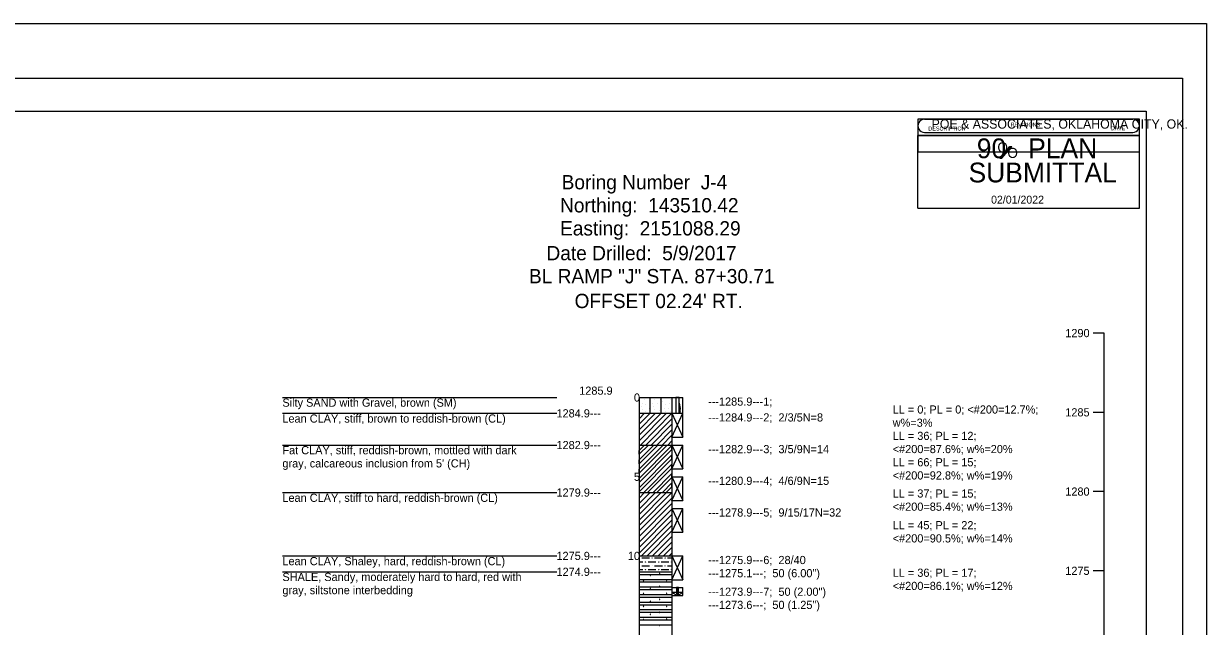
# Model space of a CAD drawing. Extents: x 2150148.6 to 2150220.1, y 143803.7 to 143875.1.
# Drawn here: x 2150182.61 to 2150200.57, y 143824.55 to 143833.69 of the extents above; entities that cross this region are included whole.
import ezdxf

# ---------------------------------------------------------------- set-up
doc = ezdxf.new("R2010")
doc.units = 0
for name, color, linetype in [('Default', 7, 'Continuous'), ('SHT_Plot_Shape_Full', 7, 'Continuous'), ('SHT_Plot_Shape_Half', 7, 'Continuous'), ('SHT_Sheet_Border', 7, 'Continuous'), ('SHT_Stamp_90_Submit', 7, 'Continuous'), ('SHT_Stamp_Rev_Block', 7, 'Continuous')]:
    doc.layers.add(name, color=color, linetype=linetype)

# ---------------------------------------------------------------- blocks, each defined once
blk = doc.blocks.new('POINT_DISPLAY')
at = {"layer": 'Default'}
blk.add_line((0, 0), (0, 0), dxfattribs=at)

msp = doc.modelspace()

# ---------------------------------------------------------------- linework, layer by layer
at = {"layer": 'Default'}
msp.add_line((2150199.025, 143815.773), (2150199.025, 143828.994), dxfattribs=at)
for points in [[(2150199.025, 143828.994), (2150198.858, 143828.994)], [(2150186.544, 143828.017), (2150190.71, 143828.017)], [(2150191.96, 143828.017), (2150191.96, 143817.921)], [(2150191.96, 143828.017), (2150192.46, 143828.017)], [(2150192.127, 143827.777), (2150192.127, 143828.017)], [(2150192.294, 143827.777), (2150192.294, 143828.017)], [(2150192.46, 143828.017), (2150192.627, 143828.017)], [(2150192.46, 143828.017), (2150192.46, 143817.921)], [(2150192.627, 143827.777), (2150192.627, 143828.017)], [(2150186.544, 143827.777), (2150190.71, 143827.777)], [(2150191.96, 143827.777), (2150192.46, 143827.777)], [(2150191.96, 143827.694), (2150192.044, 143827.777)], [(2150191.96, 143827.61), (2150192.127, 143827.777)], [(2150191.96, 143827.527), (2150192.21, 143827.777)], [(2150191.96, 143827.444), (2150192.294, 143827.777)], [(2150191.96, 143827.36), (2150192.377, 143827.777)], [(2150191.98, 143827.296), (2150192.46, 143827.777)], [(2150192.063, 143827.296), (2150192.46, 143827.694)], [(2150192.46, 143827.777), (2150192.627, 143827.777)], [(2150192.46, 143827.777), (2150192.627, 143827.416)], [(2150192.46, 143827.416), (2150192.627, 143827.777)], [(2150192.46, 143827.777), (2150192.627, 143827.777)], [(2150192.627, 143827.416), (2150192.627, 143827.777)], [(2150199.025, 143827.792), (2150198.858, 143827.792)], [(2150192.146, 143827.296), (2150192.46, 143827.61)], [(2150192.23, 143827.296), (2150192.46, 143827.527)], [(2150186.544, 143827.296), (2150190.71, 143827.296)], [(2150191.96, 143827.296), (2150192.46, 143827.296)], [(2150192.313, 143827.296), (2150192.46, 143827.444)], [(2150192.396, 143827.296), (2150192.46, 143827.36)], [(2150192.46, 143827.416), (2150192.627, 143827.416)], [(2150192.46, 143827.296), (2150192.627, 143826.936)], [(2150192.46, 143826.936), (2150192.627, 143827.296)], [(2150192.46, 143827.296), (2150192.627, 143827.296)], [(2150192.627, 143826.936), (2150192.627, 143827.296)], [(2150192.46, 143826.936), (2150192.627, 143826.936)], [(2150192.46, 143826.815), (2150192.627, 143826.455)], [(2150192.46, 143826.455), (2150192.627, 143826.815)], [(2150192.46, 143826.815), (2150192.627, 143826.815)], [(2150192.627, 143826.455), (2150192.627, 143826.815)], [(2150186.544, 143826.575), (2150190.71, 143826.575)], [(2150191.96, 143826.575), (2150192.46, 143826.575)], [(2150191.96, 143826.492), (2150192.044, 143826.575)], [(2150191.96, 143826.408), (2150192.127, 143826.575)], [(2150191.96, 143826.325), (2150192.21, 143826.575)], [(2150191.96, 143826.242), (2150192.294, 143826.575)], [(2150191.96, 143826.158), (2150192.377, 143826.575)], [(2150191.96, 143826.075), (2150192.46, 143826.575)], [(2150199.025, 143826.59), (2150198.858, 143826.59)], [(2150191.96, 143825.992), (2150192.46, 143826.492)], [(2150191.96, 143825.908), (2150192.46, 143826.408)], [(2150192.46, 143826.455), (2150192.627, 143826.455)], [(2150191.96, 143825.825), (2150192.46, 143826.325)], [(2150191.96, 143825.742), (2150192.46, 143826.242)], [(2150192.46, 143826.335), (2150192.627, 143825.974)], [(2150192.46, 143825.974), (2150192.627, 143826.335)], [(2150192.46, 143826.335), (2150192.627, 143826.335)], [(2150192.627, 143825.974), (2150192.627, 143826.335)], [(2150191.96, 143825.658), (2150192.46, 143826.158)], [(2150191.999, 143825.614), (2150192.46, 143826.075)], [(2150192.082, 143825.614), (2150192.46, 143825.992)], [(2150192.166, 143825.614), (2150192.46, 143825.908)], [(2150192.46, 143825.974), (2150192.627, 143825.974)], [(2150192.249, 143825.614), (2150192.46, 143825.825)], [(2150192.332, 143825.614), (2150192.46, 143825.742)], [(2150186.544, 143825.614), (2150190.71, 143825.614)], [(2150191.96, 143825.614), (2150192.46, 143825.614)], [(2150191.96, 143825.584), (2150191.964, 143825.584), (2150191.964, 143825.58), (2150191.96, 143825.584)], [(2150191.96, 143825.525), (2150192.019, 143825.525)], [(2150192, 143825.584), (2150192.118, 143825.584)], [(2150192.059, 143825.525), (2150192.063, 143825.525), (2150192.059, 143825.521), (2150192.059, 143825.525)], [(2150192.098, 143825.525), (2150192.216, 143825.525)], [(2150192.157, 143825.584), (2150192.161, 143825.584), (2150192.157, 143825.58), (2150192.157, 143825.584)], [(2150192.197, 143825.584), (2150192.315, 143825.584)], [(2150192.256, 143825.525), (2150192.26, 143825.525), (2150192.26, 143825.521), (2150192.256, 143825.525)], [(2150192.295, 143825.525), (2150192.354, 143825.525)], [(2150192.354, 143825.584), (2150192.358, 143825.584), (2150192.358, 143825.58), (2150192.354, 143825.584)], [(2150192.354, 143825.525), (2150192.413, 143825.525)], [(2150192.393, 143825.584), (2150192.46, 143825.584)], [(2150192.416, 143825.614), (2150192.46, 143825.658)], [(2150192.453, 143825.525), (2150192.456, 143825.525), (2150192.453, 143825.521), (2150192.453, 143825.525)], [(2150192.46, 143825.614), (2150192.627, 143825.253)], [(2150192.46, 143825.253), (2150192.627, 143825.614)], [(2150192.46, 143825.614), (2150192.627, 143825.614)], [(2150192.627, 143825.253), (2150192.627, 143825.614)], [(2150186.544, 143825.373), (2150190.71, 143825.373)], [(2150191.96, 143825.466), (2150191.964, 143825.466), (2150191.964, 143825.462), (2150191.96, 143825.466)], [(2150191.96, 143825.407), (2150192.019, 143825.407)], [(2150191.96, 143825.373), (2150192.46, 143825.373)], [(2150191.96, 143825.373), (2150192.46, 143825.373)], [(2150191.96, 143825.334), (2150192.46, 143825.334)], [(2150192, 143825.466), (2150192.118, 143825.466)], [(2150192.059, 143825.407), (2150192.063, 143825.407), (2150192.059, 143825.403), (2150192.059, 143825.407)], [(2150192.098, 143825.407), (2150192.216, 143825.407)], [(2150192.135, 143825.317), (2150192.134, 143825.32), (2150192.131, 143825.32), (2150192.129, 143825.317), (2150192.131, 143825.315), (2150192.134, 143825.315), (2150192.135, 143825.317)], [(2150192.157, 143825.466), (2150192.161, 143825.466), (2150192.157, 143825.462), (2150192.157, 143825.466)], [(2150192.197, 143825.466), (2150192.315, 143825.466)], [(2150192.256, 143825.407), (2150192.26, 143825.407), (2150192.26, 143825.403), (2150192.256, 143825.407)], [(2150192.278, 143825.349), (2150192.276, 143825.352), (2150192.273, 143825.352), (2150192.272, 143825.349), (2150192.273, 143825.346), (2150192.276, 143825.346), (2150192.278, 143825.349)], [(2150192.295, 143825.407), (2150192.354, 143825.407)], [(2150192.354, 143825.466), (2150192.358, 143825.466), (2150192.358, 143825.462), (2150192.354, 143825.466)], [(2150192.354, 143825.407), (2150192.413, 143825.407)], [(2150192.393, 143825.466), (2150192.46, 143825.466)], [(2150192.453, 143825.407), (2150192.456, 143825.407), (2150192.453, 143825.403), (2150192.453, 143825.407)], [(2150199.025, 143825.388), (2150198.858, 143825.388)], [(2150191.96, 143825.258), (2150192.46, 143825.258)], [(2150191.96, 143825.219), (2150192.46, 143825.219)], [(2150191.96, 143825.144), (2150192.46, 143825.144)], [(2150192.031, 143825.238), (2150192.029, 143825.241), (2150192.026, 143825.241), (2150192.024, 143825.238), (2150192.026, 143825.236), (2150192.029, 143825.236), (2150192.031, 143825.238)], [(2150192.135, 143825.12), (2150192.134, 143825.123), (2150192.131, 143825.123), (2150192.129, 143825.121), (2150192.131, 143825.118), (2150192.134, 143825.118), (2150192.135, 143825.12)], [(2150192.278, 143825.152), (2150192.276, 143825.155), (2150192.273, 143825.155), (2150192.272, 143825.152), (2150192.273, 143825.15), (2150192.276, 143825.15), (2150192.278, 143825.152)], [(2150192.384, 143825.245), (2150192.382, 143825.248), (2150192.379, 143825.248), (2150192.377, 143825.245), (2150192.379, 143825.242), (2150192.382, 143825.242), (2150192.384, 143825.245)], [(2150192.46, 143825.253), (2150192.627, 143825.253)], [(2150192.46, 143825.133), (2150192.627, 143825.133)], [(2150192.627, 143825.013), (2150192.627, 143825.133)], [(2150191.96, 143825.104), (2150192.46, 143825.104)], [(2150191.96, 143825.029), (2150192.46, 143825.029)], [(2150191.96, 143824.989), (2150192.46, 143824.989)], [(2150192.031, 143825.042), (2150192.029, 143825.044), (2150192.026, 143825.044), (2150192.024, 143825.042), (2150192.026, 143825.039), (2150192.029, 143825.039), (2150192.031, 143825.042)], [(2150192.278, 143824.956), (2150192.276, 143824.958), (2150192.273, 143824.958), (2150192.272, 143824.956), (2150192.273, 143824.953), (2150192.276, 143824.953), (2150192.278, 143824.956)], [(2150192.384, 143825.048), (2150192.382, 143825.051), (2150192.379, 143825.051), (2150192.377, 143825.048), (2150192.379, 143825.045), (2150192.382, 143825.045), (2150192.384, 143825.048)], [(2150192.46, 143825.013), (2150192.627, 143825.013)], [(2150191.96, 143824.914), (2150192.46, 143824.914)], [(2150191.96, 143824.874), (2150192.46, 143824.874)], [(2150191.96, 143824.799), (2150192.46, 143824.799)], [(2150192.031, 143824.845), (2150192.029, 143824.848), (2150192.026, 143824.848), (2150192.024, 143824.845), (2150192.026, 143824.842), (2150192.029, 143824.842), (2150192.031, 143824.845)], [(2150192.135, 143824.924), (2150192.134, 143824.927), (2150192.131, 143824.927), (2150192.129, 143824.924), (2150192.131, 143824.921), (2150192.134, 143824.921), (2150192.135, 143824.924)], [(2150192.384, 143824.851), (2150192.382, 143824.854), (2150192.379, 143824.854), (2150192.377, 143824.851), (2150192.379, 143824.848), (2150192.382, 143824.848), (2150192.384, 143824.851)], [(2150191.96, 143824.76), (2150192.46, 143824.76)], [(2150191.96, 143824.684), (2150192.46, 143824.684)], [(2150191.96, 143824.645), (2150192.46, 143824.645)], [(2150192.031, 143824.648), (2150192.029, 143824.651), (2150192.026, 143824.651), (2150192.024, 143824.648), (2150192.026, 143824.645), (2150192.029, 143824.645), (2150192.031, 143824.648)], [(2150192.135, 143824.727), (2150192.134, 143824.73), (2150192.131, 143824.73), (2150192.129, 143824.727), (2150192.131, 143824.724), (2150192.134, 143824.724), (2150192.135, 143824.727)], [(2150192.278, 143824.759), (2150192.276, 143824.761), (2150192.273, 143824.761), (2150192.272, 143824.759), (2150192.273, 143824.756), (2150192.276, 143824.756), (2150192.278, 143824.759)], [(2150192.384, 143824.654), (2150192.382, 143824.657), (2150192.379, 143824.657), (2150192.377, 143824.654), (2150192.379, 143824.652), (2150192.382, 143824.652), (2150192.384, 143824.654)], [(2150191.96, 143824.569), (2150192.46, 143824.569)], [(2150192.278, 143824.562), (2150192.276, 143824.565), (2150192.273, 143824.565), (2150192.272, 143824.562), (2150192.273, 143824.559), (2150192.276, 143824.559), (2150192.278, 143824.562)]]:
    msp.add_lwpolyline(points, dxfattribs=at)
for points in [[(2150192.519, 143828.017), (2150192.519, 143827.777), (2150192.569, 143827.777), (2150192.569, 143828.017)], [(2150192.569, 143827.932), (2150192.569, 143827.777), (2150192.583, 143827.851), (2150192.569, 143827.932)], [(2150192.569, 143827.932), (2150192.583, 143827.851), (2150192.577, 143827.892), (2150192.569, 143827.932)], [(2150192.569, 143827.777), (2150192.585, 143827.809), (2150192.583, 143827.851), (2150192.569, 143827.777)], [(2150192.569, 143827.777), (2150192.584, 143827.777), (2150192.585, 143827.809), (2150192.569, 143827.777)], [(2150191.96, 143826.93), (2150192.327, 143827.296), (2150192.385, 143827.296), (2150191.96, 143826.871)], [(2150191.96, 143827.071), (2150192.185, 143827.296), (2150192.244, 143827.296), (2150191.96, 143827.013)], [(2150191.96, 143827.213), (2150192.044, 143827.296), (2150192.102, 143827.296), (2150191.96, 143827.155)], [(2150192.46, 143827.23), (2150192.46, 143827.288), (2150191.961, 143826.788), (2150191.961, 143826.73)], [(2150192.46, 143827.088), (2150192.46, 143827.146), (2150191.961, 143826.646), (2150191.961, 143826.588)], [(2150192.46, 143826.946), (2150192.46, 143827.005), (2150192.031, 143826.575), (2150192.089, 143826.575)], [(2150192.46, 143826.805), (2150192.46, 143826.863), (2150192.173, 143826.575), (2150192.231, 143826.575)], [(2150192.46, 143826.663), (2150192.46, 143826.721), (2150192.314, 143826.575), (2150192.373, 143826.575)], [(2150192.456, 143826.575), (2150192.46, 143826.575), (2150192.46, 143826.58), (2150192.456, 143826.575)], [(2150192.527, 143825.061), (2150192.56, 143825.061), (2150192.56, 143825.133), (2150192.527, 143825.061)], [(2150192.527, 143825.061), (2150192.56, 143825.133), (2150192.527, 143825.133), (2150192.527, 143825.061)], [(2150192.527, 143825.061), (2150192.46, 143825.061), (2150192.544, 143825.013), (2150192.527, 143825.061)], [(2150192.527, 143825.061), (2150192.544, 143825.013), (2150192.56, 143825.061), (2150192.527, 143825.061)], [(2150192.544, 143825.013), (2150192.627, 143825.061), (2150192.56, 143825.061), (2150192.544, 143825.013)]]:
    msp.add_lwpolyline(points, close=True, dxfattribs=at)
at = {"layer": 'SHT_Plot_Shape_Full'}
msp.add_lwpolyline([(2150164.575, 143833.688), (2150200.575, 143833.688), (2150200.575, 143809.688), (2150164.575, 143809.688)], close=True, dxfattribs=at)
at = {"layer": 'SHT_Plot_Shape_Half'}
msp.add_lwpolyline([(2150166.212, 143832.863), (2150200.212, 143832.863), (2150200.212, 143810.863), (2150166.212, 143810.863)], close=True, dxfattribs=at)
at = {"layer": 'SHT_Sheet_Border'}
msp.add_lwpolyline([(2150199.662, 143811.363), (2150168.162, 143811.363), (2150168.162, 143832.363), (2150199.662, 143832.363)], close=True, dxfattribs=at)
at = {"layer": 'SHT_Stamp_90_Submit'}
for p, q in [((2150196.293, 143832.239), (2150199.459, 143832.239)), ((2150196.193, 143831.989), (2150199.559, 143831.989)), ((2150196.193, 143830.889), (2150196.193, 143831.989)), ((2150196.293, 143832.039), (2150199.459, 143832.039)), ((2150199.559, 143830.889), (2150199.559, 143831.989)), ((2150197.437, 143831.65), (2150197.592, 143831.823)), ((2150197.454, 143831.65), (2150197.61, 143831.823)), ((2150197.459, 143831.65), (2150197.615, 143831.823)), ((2150197.467, 143831.65), (2150197.623, 143831.823)), ((2150197.592, 143831.823), (2150197.623, 143831.823)), ((2150197.437, 143831.65), (2150197.467, 143831.65)), ((2150196.193, 143830.889), (2150199.559, 143830.889))]:
    msp.add_line(p, q, dxfattribs=at)
for centre, start, end in [((2150196.294, 143832.139), 89.9952, 270), ((2150199.46, 143832.139), 270, 90.0048)]:
    msp.add_arc(centre, 0.1, start, end, dxfattribs=at)
at = {"layer": 'SHT_Stamp_Rev_Block'}
for p, q in [((2150196.194, 143832.239), (2150196.194, 143831.739)), ((2150199.559, 143832.239), (2150196.194, 143832.239)), ((2150199.559, 143831.739), (2150199.559, 143832.239)), ((2150199.559, 143831.989), (2150196.194, 143831.989)), ((2150199.559, 143831.739), (2150196.194, 143831.739))]:
    msp.add_line(p, q, dxfattribs=at)

# ---------------------------------------------------------------- block references
at = {"layer": 'Default', "xscale": 0.39369999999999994, "yscale": 0.3936999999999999}
for p in [(2150191.99, 143828.005), (2150192.115, 143828.005), (2150192.365, 143828.005), (2150191.965, 143827.955), (2150191.99, 143827.88), (2150192.015, 143827.93), (2150192.015, 143827.83), (2150192.04, 143827.98), (2150192.065, 143827.905), (2150192.115, 143827.855), (2150192.132, 143827.957), (2150192.165, 143827.93), (2150192.177, 143827.873), (2150192.19, 143827.98), (2150192.19, 143827.83), (2150192.24, 143827.93), (2150192.278, 143827.816), (2150192.28, 143827.992), (2150192.29, 143827.88), (2150192.315, 143827.955), (2150192.347, 143827.851), (2150192.365, 143827.905), (2150192.407, 143827.848), (2150192.415, 143827.93), (2150192.44, 143827.98), (2150192.456, 143827.855), (2150191.965, 143827.78), (2150192.065, 143827.805), (2150192.129, 143827.797), (2150192.315, 143827.78), (2150192.365, 143827.805), (2150192.44, 143827.805)]:
    msp.add_blockref('POINT_DISPLAY', p, dxfattribs=at)

# ---------------------------------------------------------------- texts
at = {"layer": 'Default'}
for s, height, p in [('Boring Number  J-4', 0.217, (2150190.784, 143831.175)), ('Northing:  143510.42', 0.217, (2150190.76, 143830.825)), ('Easting:  2151088.29', 0.217, (2150190.76, 143830.475)), ('Date Drilled:  5/9/2017', 0.217, (2150190.554, 143830.099)), ('BL RAMP "J" STA. 87+30.71', 0.217, (2150190.288, 143829.749)), ("OFFSET 02.24' RT.", 0.217, (2150190.981, 143829.373)), ('1290', 0.124, (2150198.433, 143828.932)), ('1285.9', 0.124, (2150191.051, 143828.059)), ('Silty SAND with Gravel, brown (SM)', 0.124, (2150186.544, 143827.877)), ('0', 0.124, (2150191.882, 143827.955)), ('---1285.9---1;', 0.124, (2150193.008, 143827.893)), ('1284.9---', 0.124, (2150190.706, 143827.715)), ('LL = 0; PL = 0; <#200=12.7%;', 0.124, (2150195.812, 143827.773)), ('1285', 0.124, (2150198.433, 143827.73)), ('Lean CLAY, stiff, brown to reddish-brown (CL)', 0.124, (2150186.544, 143827.636)), ('---1284.9---2;  2/3/5N=8', 0.124, (2150193.008, 143827.653)), ('w%=3%', 0.124, (2150195.812, 143827.573)), ('LL = 36; PL = 12;', 0.124, (2150195.812, 143827.373)), ('Fat CLAY, stiff, reddish-brown, mottled with dark', 0.124, (2150186.544, 143827.156)), ('1282.9---', 0.124, (2150190.706, 143827.234)), ('---1282.9---3;  3/5/9N=14', 0.124, (2150193.008, 143827.172)), ('<#200=87.6%; w%=20%', 0.124, (2150195.812, 143827.173)), ('LL = 66; PL = 15;', 0.124, (2150195.812, 143826.973)), ("gray, calcareous inclusion from 5' (CH)", 0.124, (2150186.544, 143826.956)), ('5', 0.124, (2150191.882, 143826.753)), ('---1280.9---4;  4/6/9N=15', 0.124, (2150193.008, 143826.691)), ('<#200=92.8%; w%=19%', 0.124, (2150195.812, 143826.773)), ('Lean CLAY, stiff to hard, reddish-brown (CL)', 0.124, (2150186.544, 143826.434)), ('1279.9---', 0.124, (2150190.706, 143826.513)), ('LL = 37; PL = 15;', 0.124, (2150195.812, 143826.499)), ('1280', 0.124, (2150198.433, 143826.528)), ('<#200=85.4%; w%=13%', 0.124, (2150195.812, 143826.299)), ('---1278.9---5;  9/15/17N=32', 0.124, (2150193.008, 143826.211)), ('LL = 45; PL = 22;', 0.124, (2150195.812, 143826.018)), ('<#200=90.5%; w%=14%', 0.124, (2150195.812, 143825.818)), ('1275.9---', 0.124, (2150190.706, 143825.552)), ('10', 0.124, (2150191.79, 143825.552)), ('Lean CLAY, Shaley, hard, reddish-brown (CL)', 0.124, (2150186.544, 143825.473)), ('---1275.9---6;  28/40', 0.124, (2150193.008, 143825.49)), ('SHALE, Sandy, moderately hard to hard, red with', 0.124, (2150186.544, 143825.233)), ('1274.9---', 0.124, (2150190.706, 143825.311)), ('---1275.1---;  50 (6.00")', 0.124, (2150193.008, 143825.29)), ('LL = 36; PL = 17;', 0.124, (2150195.812, 143825.297)), ('1275', 0.124, (2150198.433, 143825.326)), ('gray, siltstone interbedding', 0.124, (2150186.544, 143825.033)), ('---1273.9---7;  50 (2.00")', 0.124, (2150193.008, 143825.009)), ('<#200=86.1%; w%=12%', 0.124, (2150195.812, 143825.097)), ('---1273.6---;  50 (1.25")', 0.124, (2150193.008, 143824.809))]:
    msp.add_text(s, height=height, dxfattribs=at).set_placement(p)
at = {"layer": 'SHT_Stamp_90_Submit'}
for s, height, p in [('POE & ASSOCIATES, OKLAHOMA CITY, OK.', 0.14, (2150196.403, 143832.096)), ('90   PLAN', 0.3, (2150197.089, 143831.647)), ('O', 0.153, (2150197.402, 143831.735)), ('O', 0.153, (2150197.554, 143831.651)), ('SUBMITTAL', 0.3, (2150196.964, 143831.28)), ('02/01/2022', 0.12, (2150197.306, 143830.958))]:
    msp.add_text(s, height=height, dxfattribs=at).set_placement(p)
at = {"layer": 'SHT_Stamp_Rev_Block'}
for s, height, p in [('DESCRIPTION', 0.05999, (2150196.353, 143832.067)), ('REVISIONS', 0.06, (2150197.602, 143832.126)), ('DATE', 0.06, (2150199.123, 143832.071))]:
    msp.add_text(s, height=height, dxfattribs=at).set_placement(p)

doc.saveas('drawing.dxf')
